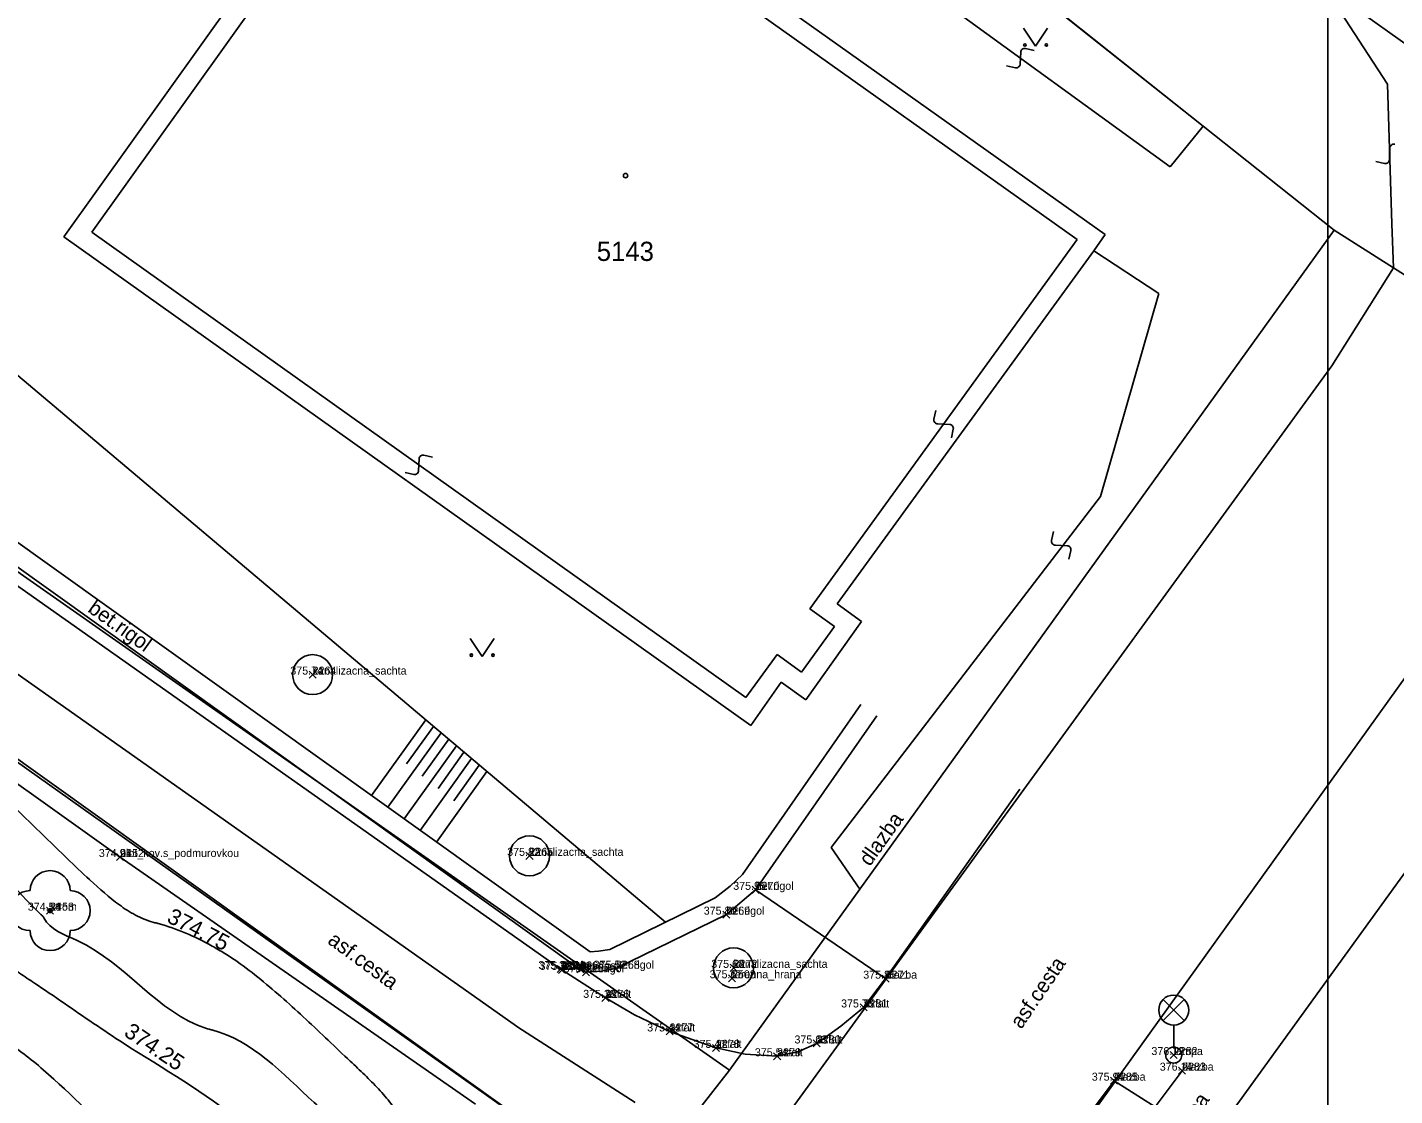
# Model space of a CAD drawing. Extents: x -400488 to -400124, y -1251493 to -1251223.
# Drawn here: x -400282.93 to -400248.76, y -1251353.83 to -1251327.13 of the extents above; entities that cross this region are included whole.
import ezdxf

# ---------------------------------------------------------------- set-up
doc = ezdxf.new("R2010")
doc.units = 0
for name, color, linetype in [('Level 20', 7, 'Continuous'), ('Level 21', 7, 'Continuous'), ('Level 22', 7, 'Continuous'), ('Level 23', 7, 'Continuous'), ('Level 3', 7, 'Continuous'), ('Level 31', 7, 'Continuous'), ('Level 32', 7, 'Continuous'), ('Level 35', 7, 'Continuous'), ('Level 36', 7, 'Continuous'), ('Level 49', 7, 'Continuous'), ('Level 52', 7, 'Continuous'), ('Level 53', 7, 'Continuous'), ('Level 63', 7, 'Continuous')]:
    doc.layers.add(name, color=color, linetype=linetype)

msp = doc.modelspace()

# ---------------------------------------------------------------- linework, layer by layer
at = {"layer": 'Level 20'}
for p, q in [((-400275.888, -1251343.398), (-400275.712, -1251343.222)), ((-400275.712, -1251343.398), (-400275.888, -1251343.222)), ((-400280.698, -1251347.958), (-400280.522, -1251347.782)), ((-400280.522, -1251347.958), (-400280.698, -1251347.782)), ((-400270.468, -1251347.928), (-400270.292, -1251347.752)), ((-400270.292, -1251347.928), (-400270.468, -1251347.752)), ((-400264.818, -1251348.778), (-400264.642, -1251348.602)), ((-400264.642, -1251348.778), (-400264.818, -1251348.602)), ((-400282.448, -1251349.298), (-400282.272, -1251349.122)), ((-400282.272, -1251349.298), (-400282.448, -1251349.122)), ((-400265.548, -1251349.398), (-400265.372, -1251349.222)), ((-400265.372, -1251349.398), (-400265.548, -1251349.222)), ((-400269.688, -1251350.758), (-400269.512, -1251350.582)), ((-400269.512, -1251350.758), (-400269.688, -1251350.582)), ((-400269.658, -1251350.778), (-400269.482, -1251350.602)), ((-400269.482, -1251350.778), (-400269.658, -1251350.602)), ((-400269.198, -1251350.768), (-400269.022, -1251350.592)), ((-400269.022, -1251350.768), (-400269.198, -1251350.592)), ((-400269.058, -1251350.838), (-400268.882, -1251350.662)), ((-400268.882, -1251350.838), (-400269.058, -1251350.662)), ((-400268.308, -1251350.748), (-400268.132, -1251350.572)), ((-400268.132, -1251350.748), (-400268.308, -1251350.572)), ((-400265.368, -1251350.728), (-400265.192, -1251350.552)), ((-400265.192, -1251350.728), (-400265.368, -1251350.552)), ((-400265.408, -1251350.988), (-400265.232, -1251350.812)), ((-400265.232, -1251350.988), (-400265.408, -1251350.812)), ((-400261.568, -1251350.998), (-400261.392, -1251350.822)), ((-400261.392, -1251350.998), (-400261.568, -1251350.822)), ((-400268.568, -1251351.478), (-400268.392, -1251351.302)), ((-400268.392, -1251351.478), (-400268.568, -1251351.302)), ((-400262.118, -1251351.718), (-400261.942, -1251351.542)), ((-400261.942, -1251351.718), (-400262.118, -1251351.542)), ((-400266.968, -1251352.318), (-400266.792, -1251352.142)), ((-400266.792, -1251352.318), (-400266.968, -1251352.142)), ((-400265.808, -1251352.728), (-400265.632, -1251352.552)), ((-400265.632, -1251352.728), (-400265.808, -1251352.552)), ((-400263.288, -1251352.618), (-400263.112, -1251352.442)), ((-400263.112, -1251352.618), (-400263.288, -1251352.442)), ((-400254.368, -1251352.908), (-400254.192, -1251352.732)), ((-400254.192, -1251352.908), (-400254.368, -1251352.732)), ((-400264.278, -1251352.938), (-400264.102, -1251352.762)), ((-400264.102, -1251352.938), (-400264.278, -1251352.762)), ((-400255.858, -1251353.548), (-400255.682, -1251353.372)), ((-400255.682, -1251353.548), (-400255.858, -1251353.372)), ((-400254.158, -1251353.298), (-400253.982, -1251353.122)), ((-400253.982, -1251353.298), (-400254.158, -1251353.122))]:
    msp.add_line(p, q, dxfattribs=at)
at = {"layer": 'Level 3'}
msp.add_lwpolyline([(-400397.431, -1251233.087), (-400250.431, -1251233.087), (-400250.431, -1251440.987), (-400397.431, -1251440.987)], close=True, dxfattribs=at)
at = {"layer": 'Level 31'}
for p, q in [((-400272.972, -1251344.443), (-400274.326, -1251346.336)), ((-400272.59, -1251344.766), (-400273.92, -1251346.625)), ((-400272.781, -1251344.605), (-400273.452, -1251345.543)), ((-400272.208, -1251345.088), (-400273.515, -1251346.915)), ((-400272.399, -1251344.927), (-400273.058, -1251345.849)), ((-400271.826, -1251345.411), (-400273.109, -1251347.205)), ((-400272.017, -1251345.249), (-400272.665, -1251346.155)), ((-400271.444, -1251345.733), (-400272.704, -1251347.495)), ((-400271.635, -1251345.572), (-400272.271, -1251346.461))]:
    msp.add_line(p, q, dxfattribs=at)
for points in [[(-400318.26, -1251315.35), (-400312.96, -1251313.03), (-400288.36, -1251331.46), (-400266.982, -1251349.498)], [(-400316.14, -1251315.89), (-400316.44, -1251316.29), (-400297.85, -1251330.26), (-400287.82, -1251337.3), (-400269.11, -1251350.68), (-400268.97, -1251350.75), (-400268.595, -1251350.721), (-400268.22, -1251350.66), (-400265.46, -1251349.31), (-400264.73, -1251348.69)], [(-400316.14, -1251315.89), (-400297.556, -1251329.855), (-400287.531, -1251336.892), (-400268.865, -1251350.24), (-400268.655, -1251350.224), (-400268.373, -1251350.178), (-400265.736, -1251348.888), (-400265.364, -1251348.599), (-400265.054, -1251348.309), (-400262.095, -1251344.059)], [(-400261.696, -1251344.337), (-400264.73, -1251348.69), (-400261.48, -1251350.91)], [(-400254.07, -1251353.21), (-400254.74, -1251354.11), (-400255.77, -1251353.46)]]:
    msp.add_lwpolyline(points, dxfattribs=at)
at = {"layer": 'Level 32'}
for points in [[(-400312.5, -1251319.48), (-400297.6, -1251330.92), (-400269.6, -1251350.67), (-400269.57, -1251350.69), (-400268.48, -1251351.39), (-400267.759, -1251351.812), (-400266.88, -1251352.23), (-400265.72, -1251352.64), (-400264.993, -1251352.795), (-400264.19, -1251352.85), (-400263.653, -1251352.732), (-400263.2, -1251352.53), (-400262.601, -1251352.1), (-400262.03, -1251351.63), (-400261.48, -1251350.91)], [(-400313.317, -1251321.122), (-400298.667, -1251332.37), (-400270.618, -1251352.155), (-400270.556, -1251352.196), (-400267.742, -1251354.003)], [(-400261.48, -1251350.91), (-400258.127, -1251346.175)], [(-400255.77, -1251353.46), (-400257.84, -1251356.24)]]:
    msp.add_lwpolyline(points, dxfattribs=at)
at = {"layer": 'Level 35'}
for points in [[(-400271.73, -1251354.05), (-400280.61, -1251347.87), (-400289.94, -1251341.22), (-400298.73, -1251334.93), (-400304.55, -1251330.65), (-400304.36, -1251330.4)], [(-400304.36, -1251330.4), (-400289.76, -1251340.83), (-400270.68, -1251354.37)]]:
    msp.add_lwpolyline(points, dxfattribs=at)
at = {"layer": 'Level 36'}
for q in [(-400271.863, -1251342.404), (-400271.263, -1251342.404)]:
    msp.add_line((-400271.563, -1251342.854), q, dxfattribs=at)
for centre, radius in [((-400271.833, -1251342.824), 0.03), ((-400271.293, -1251342.824), 0.03), ((-400282.36, -1251349.21), 0.05)]:
    msp.add_circle(centre, radius, dxfattribs=at)
for centre, start, end in [((-400282.36, -1251348.71), 0, 180), ((-400282.86, -1251349.21), 90, 270), ((-400281.86, -1251349.21), 270, 90), ((-400282.36, -1251349.71), 180, 0)]:
    msp.add_arc(centre, 0.5, start, end, dxfattribs=at)
at = {"layer": 'Level 49'}
for points in [[(-400278.631, -1251370.004), (-400278.118, -1251366.954), (-400277.412, -1251363.928), (-400277.404, -1251363.9), (-400277.243, -1251363.447), (-400277.063, -1251363.002), (-400276.883, -1251362.554), (-400276.725, -1251362.096), (-400276.548, -1251361.022), (-400276.561, -1251359.49), (-400276.508, -1251355.66), (-400276.495, -1251355.542), (-400276.499, -1251355.304), (-400276.5, -1251355.302), (-400276.561, -1251355.147), (-400276.562, -1251355.145), (-400276.659, -1251355.037), (-400276.991, -1251354.829), (-400277.106, -1251354.817), (-400277.114, -1251354.814), (-400277.554, -1251354.518), (-400280.527, -1251352.524), (-400282.011, -1251351.524), (-400282.752, -1251351.021), (-400283.123, -1251350.771), (-400283.308, -1251350.645), (-400283.491, -1251350.515), (-400283.5, -1251350.503), (-400283.513, -1251350.487), (-400283.613, -1251350.393), (-400283.723, -1251350.31), (-400283.834, -1251350.228), (-400283.937, -1251350.138), (-400285.14, -1251348.868), (-400286.294, -1251347.546), (-400287.449, -1251346.222), (-400288.656, -1251344.945), (-400289.834, -1251343.824), (-400290.459, -1251343.304), (-400291.116, -1251342.818), (-400291.123, -1251342.814), (-400295.387, -1251340.816), (-400295.481, -1251340.776), (-400295.888, -1251340.55), (-400296.417, -1251340.117), (-400298.55, -1251337.977), (-400299.765, -1251336.773), (-400300.345, -1251336.13), (-400300.624, -1251335.775), (-400300.759, -1251335.587), (-400300.892, -1251335.391), (-400300.889, -1251335.373), (-400300.892, -1251335.36), (-400300.967, -1251335.291), (-400301.043, -1251335.241), (-400301.201, -1251335.182), (-400301.531, -1251335.135), (-400302.215, -1251335.034), (-400302.251, -1251335.031), (-400302.332, -1251334.999), (-400303.687, -1251334.283), (-400305.005, -1251333.533), (-400306.96, -1251332.166)], [(-400282.087, -1251375.169), (-400281.69, -1251370.822), (-400281.381, -1251368.586), (-400280.551, -1251363.9), (-400280.546, -1251363.886), (-400280.15, -1251362.887), (-400279.737, -1251361.896), (-400279.326, -1251360.9), (-400278.941, -1251359.886), (-400278.883, -1251359.562), (-400278.885, -1251359.094), (-400279.241, -1251356.971), (-400279.631, -1251356.354), (-400280.512, -1251355.223), (-400282.534, -1251353.186), (-400283.018, -1251352.792), (-400283.53, -1251352.437), (-400284.027, -1251352.07), (-400284.466, -1251351.641), (-400284.483, -1251351.618), (-400284.488, -1251351.612), (-400285.314, -1251350.99), (-400287.151, -1251349.31), (-400292.845, -1251345.168), (-400292.862, -1251345.159), (-400295.431, -1251343.95), (-400295.488, -1251343.921), (-400297.591, -1251342.594), (-400300.391, -1251340.357), (-400303.398, -1251337.509), (-400303.407, -1251337.499), (-400305.011, -1251335.906), (-400306.002, -1251335.061), (-400307.028, -1251334.259), (-400308.006, -1251333.512)], [(-400274.109, -1251364.042), (-400274.008, -1251363.383), (-400273.954, -1251363.053), (-400273.943, -1251362.724), (-400273.958, -1251362.626), (-400273.997, -1251362.507), (-400274.011, -1251362.47), (-400274.012, -1251362.468), (-400274.162, -1251361.825), (-400274.25, -1251361.177), (-400274.313, -1251359.872), (-400274.338, -1251357.988), (-400274.341, -1251357.92), (-400274.598, -1251355.942), (-400274.603, -1251355.924), (-400275.052, -1251354.804), (-400275.058, -1251354.792), (-400275.759, -1251354.005), (-400278.319, -1251352.191), (-400278.397, -1251352.171), (-400278.453, -1251352.154), (-400281.685, -1251349.955), (-400282.516, -1251349.39), (-400282.517, -1251349.388), (-400282.537, -1251349.359), (-400282.59, -1251349.305), (-400284.983, -1251346.43), (-400288.552, -1251342.393)], [(-400271.965, -1251360.814), (-400272.009, -1251360.689), (-400272.186, -1251360.237), (-400272.197, -1251360.198), (-400272.225, -1251359.97), (-400272.697, -1251356.579), (-400272.706, -1251356.547), (-400273.542, -1251354.461), (-400273.554, -1251354.438), (-400273.691, -1251354.234), (-400273.837, -1251354.037), (-400274.155, -1251353.667), (-400274.498, -1251353.316), (-400274.859, -1251352.974), (-400275.963, -1251351.93), (-400277.098, -1251350.932), (-400277.684, -1251350.485), (-400277.992, -1251350.283), (-400278.313, -1251350.095), (-400278.97, -1251349.772), (-400279.657, -1251349.533), (-400279.687, -1251349.525), (-400279.791, -1251349.497), (-400280.227, -1251349.321), (-400280.628, -1251349.067), (-400281.363, -1251348.446), (-400281.375, -1251348.435), (-400282.483, -1251347.375), (-400283.583, -1251346.308), (-400284.682, -1251345.24), (-400284.836, -1251345.091)]]:
    msp.add_spline(points, degree=3, dxfattribs=at)
at = {"layer": 'Level 52'}
for centre in [(-400275.8, -1251343.31), (-400270.38, -1251347.84), (-400265.28, -1251350.64)]:
    msp.add_circle(centre, 0.5, dxfattribs=at)
at = {"layer": 'Level 53'}
for p, q in [((-400254.545, -1251351.96), (-400254.015, -1251351.43)), ((-400254.015, -1251351.43), (-400254.545, -1251351.96)), ((-400254.015, -1251351.96), (-400254.545, -1251351.43)), ((-400254.28, -1251352.07), (-400254.28, -1251352.62))]:
    msp.add_line(p, q, dxfattribs=at)
for centre, radius in [((-400254.28, -1251351.695), 0.375), ((-400254.28, -1251352.82), 0.2)]:
    msp.add_circle(centre, radius, dxfattribs=at)
at = {"layer": 'Level 63'}
for p, q in [((-400255.99, -1251332.31), (-400273.23, -1251320.07)), ((-400273.23, -1251320.07), (-400255.99, -1251332.31)), ((-400273.11, -1251320.77), (-400256.69, -1251332.43)), ((-400273.87, -1251320.97), (-400282.02, -1251332.37)), ((-400282.02, -1251332.37), (-400273.87, -1251320.97)), ((-400281.32, -1251332.25), (-400273.46, -1251321.26)), ((-400260.82, -1251323.81), (-400253.54, -1251329.6)), ((-400253.54, -1251329.6), (-400260.82, -1251323.81)), ((-400254.37, -1251330.62), (-400261.85, -1251325.18)), ((-400248.94, -1251328.55), (-400250.54, -1251326.08)), ((-400237.21, -1251335.61), (-400250.54, -1251326.08)), ((-400258.03, -1251327.15), (-400257.73, -1251327.6)), ((-400257.73, -1251327.6), (-400257.43, -1251327.15)), ((-400308.16, -1251327.55), (-400270.88, -1251354.21)), ((-400270.88, -1251354.21), (-400308.16, -1251327.55)), ((-400258.116, -1251328.047), (-400258.104, -1251327.753)), ((-400257.983, -1251327.659), (-400257.765, -1251327.707)), ((-400258.455, -1251328.093), (-400258.237, -1251328.141)), ((-400248.83, -1251332.04), (-400248.94, -1251328.55)), ((-400253.54, -1251329.6), (-400254.37, -1251330.62)), ((-400253.54, -1251329.6), (-400250.27, -1251332.2)), ((-400250.27, -1251332.2), (-400253.54, -1251329.6)), ((-400248.891, -1251330.442), (-400248.879, -1251330.148)), ((-400249.23, -1251330.488), (-400249.012, -1251330.536)), ((-400265.38, -1251353.2), (-400297.73, -1251330.54)), ((-400297.73, -1251330.54), (-400265.38, -1251353.2)), ((-400262.12, -1251348.67), (-400250.27, -1251332.2)), ((-400250.27, -1251332.2), (-400262.12, -1251348.67)), ((-400250.27, -1251332.2), (-400248.79, -1251333.14)), ((-400248.79, -1251333.14), (-400250.27, -1251332.2)), ((-400248.79, -1251333.14), (-400248.83, -1251332.04)), ((-400282.02, -1251332.37), (-400264.85, -1251344.58)), ((-400264.85, -1251344.58), (-400282.02, -1251332.37)), ((-400264.97, -1251343.88), (-400281.32, -1251332.25)), ((-400256.69, -1251332.43), (-400263.37, -1251341.67)), ((-400256.28, -1251332.72), (-400255.99, -1251332.31)), ((-400255.99, -1251332.31), (-400256.28, -1251332.72)), ((-400262.69, -1251341.54), (-400256.28, -1251332.72)), ((-400256.28, -1251332.72), (-400262.69, -1251341.54)), ((-400256.28, -1251332.72), (-400254.65, -1251333.78)), ((-400248.79, -1251333.14), (-400250.33, -1251335.59)), ((-400248.79, -1251333.14), (-400243.42, -1251336.59)), ((-400243.42, -1251336.59), (-400248.79, -1251333.14)), ((-400254.65, -1251333.78), (-400256.11, -1251338.86)), ((-400250.33, -1251335.59), (-400267.74, -1251359.55)), ((-400260.271, -1251336.923), (-400260.223, -1251336.705)), ((-400259.883, -1251337.056), (-400260.177, -1251337.044)), ((-400259.837, -1251337.395), (-400259.789, -1251337.177)), ((-400273.151, -1251338.212), (-400273.139, -1251337.918)), ((-400273.018, -1251337.824), (-400272.8, -1251337.872)), ((-400244.75, -1251338.16), (-400287.97, -1251398.37)), ((-400273.49, -1251338.258), (-400273.272, -1251338.306)), ((-400256.11, -1251338.86), (-400262.84, -1251347.63)), ((-400257.331, -1251339.955), (-400257.283, -1251339.737)), ((-400253.66, -1251355.39), (-400242.23, -1251339.57)), ((-400242.23, -1251339.57), (-400253.66, -1251355.39)), ((-400256.943, -1251340.087), (-400257.237, -1251340.076)), ((-400256.897, -1251340.426), (-400256.849, -1251340.208)), ((-400263.37, -1251341.67), (-400262.76, -1251342.11)), ((-400262.08, -1251341.98), (-400262.69, -1251341.54)), ((-400262.69, -1251341.54), (-400262.08, -1251341.98)), ((-400262.76, -1251342.11), (-400263.58, -1251343.25)), ((-400263.47, -1251343.94), (-400262.08, -1251341.98)), ((-400262.08, -1251341.98), (-400263.47, -1251343.94)), ((-400264.19, -1251342.81), (-400264.97, -1251343.88)), ((-400263.58, -1251343.25), (-400264.19, -1251342.81)), ((-400264.85, -1251344.58), (-400264.09, -1251343.5)), ((-400264.09, -1251343.5), (-400264.85, -1251344.58)), ((-400264.09, -1251343.5), (-400263.47, -1251343.94)), ((-400263.47, -1251343.94), (-400264.09, -1251343.5)), ((-400262.84, -1251347.63), (-400262.12, -1251348.67)), ((-400265.38, -1251353.2), (-400262.12, -1251348.67)), ((-400262.12, -1251348.67), (-400265.38, -1251353.2)), ((-400270.09, -1251359.2), (-400265.38, -1251353.2)), ((-400265.38, -1251353.2), (-400270.09, -1251359.2))]:
    msp.add_line(p, q, dxfattribs=at)
for centre, radius in [((-400258, -1251327.57), 0.03), ((-400257.46, -1251327.57), 0.03), ((-400267.98, -1251330.836), 0.054)]:
    msp.add_circle(centre, radius, dxfattribs=at)
for centre, start, end in [((-400258.004, -1251327.757), 77.7527, 177.7631), ((-400258.216, -1251328.043), 257.753, 357.7631), ((-400248.779, -1251330.152), 77.7527, 177.7631), ((-400248.991, -1251330.438), 257.753, 357.7631), ((-400260.173, -1251336.944), 167.7527, 267.7631), ((-400259.887, -1251337.156), 347.753, 87.7631), ((-400273.039, -1251337.922), 77.7527, 177.7631), ((-400273.251, -1251338.208), 257.753, 357.7631), ((-400257.233, -1251339.976), 167.7527, 267.7631), ((-400256.947, -1251340.187), 347.753, 87.7631)]:
    msp.add_arc(centre, 0.1, start, end, dxfattribs=at)

# ---------------------------------------------------------------- texts
at = {"layer": 'Level 21'}
for s, p in [('2264', (-400275.8, -1251343.31)), ('2452', (-400280.61, -1251347.87)), ('2265', (-400270.38, -1251347.84)), ('2270', (-400264.73, -1251348.69)), ('2453', (-400282.36, -1251349.21)), ('2269', (-400265.46, -1251349.31)), ('2274', (-400269.6, -1251350.67)), ('2275', (-400269.57, -1251350.69)), ('2266', (-400269.11, -1251350.68)), ('2267', (-400268.97, -1251350.75)), ('2268', (-400268.22, -1251350.66)), ('2272', (-400265.28, -1251350.64)), ('2508', (-400265.32, -1251350.9)), ('2271', (-400261.48, -1251350.91)), ('2276', (-400268.48, -1251351.39)), ('2281', (-400262.03, -1251351.63)), ('2277', (-400266.88, -1251352.23)), ('2280', (-400263.2, -1251352.53)), ('2278', (-400265.72, -1251352.64)), ('2279', (-400264.19, -1251352.85)), ('2282', (-400254.28, -1251352.82)), ('2283', (-400254.07, -1251353.21)), ('2285', (-400255.77, -1251353.46))]:
    msp.add_text(s, height=0.2, dxfattribs=at).set_placement(p)
at = {"layer": 'Level 22'}
for s, p in [('kanalizacna_sachta', (-400275.8, -1251343.31)), ('plot_kov.s_podmurovkou', (-400280.61, -1251347.87)), ('kanalizacna_sachta', (-400270.38, -1251347.84)), ('bet.rigol', (-400264.73, -1251348.69)), ('strom', (-400282.36, -1251349.21)), ('bet.rigol', (-400265.46, -1251349.31)), ('asfalt', (-400269.6, -1251350.67)), ('asfalt', (-400269.57, -1251350.69)), ('bet.rigol', (-400269.11, -1251350.68)), ('bet.rigol', (-400268.97, -1251350.75)), ('bet.rigol', (-400268.22, -1251350.66)), ('terenna_hrana', (-400265.32, -1251350.9)), ('kanalizacna_sachta', (-400265.28, -1251350.64)), ('dlazba', (-400261.48, -1251350.91)), ('asfalt', (-400268.48, -1251351.39)), ('asfalt', (-400262.03, -1251351.63)), ('asfalt', (-400266.88, -1251352.23)), ('asfalt', (-400263.2, -1251352.53)), ('asfalt', (-400265.72, -1251352.64)), ('asfalt', (-400264.19, -1251352.85)), ('lampa', (-400254.28, -1251352.82)), ('dlazba', (-400254.07, -1251353.21)), ('dlazba', (-400255.77, -1251353.46))]:
    msp.add_text(s, height=0.2, dxfattribs=at).set_placement(p)
at = {"layer": 'Level 23'}
for s, p in [('375.74', (-400276.358, -1251343.31)), ('374.91', (-400281.143, -1251347.87)), ('375.82', (-400270.938, -1251347.84)), ('375.95', (-400265.289, -1251348.69)), ('374.54', (-400282.918, -1251349.21)), ('375.80', (-400266.026, -1251349.31)), ('375.38', (-400270.158, -1251350.67)), ('375.38', (-400270.128, -1251350.69)), ('375.41', (-400269.643, -1251350.68)), ('375.43', (-400269.528, -1251350.75)), ('375.52', (-400268.778, -1251350.66)), ('375.68', (-400265.838, -1251350.64)), ('375.67', (-400265.878, -1251350.9)), ('375.85', (-400262.039, -1251350.91)), ('375.38', (-400269.038, -1251351.39)), ('375.76', (-400262.593, -1251351.63)), ('375.44', (-400267.438, -1251352.23)), ('375.63', (-400263.758, -1251352.53)), ('375.47', (-400266.278, -1251352.64)), ('375.54', (-400264.748, -1251352.85)), ('376.12', (-400254.838, -1251352.82)), ('376.14', (-400254.628, -1251353.21)), ('375.94', (-400256.328, -1251353.46))]:
    msp.add_text(s, height=0.2, dxfattribs=at).set_placement(p)
at = {"layer": 'Level 31'}
for s, rotation, p in [('bet.rigol', 324.5461, (-400281.444, -1251341.724)), ('dlazba', 54.566, (-400261.873, -1251348.123)), ('dlazba', 54.566, (-400254.224, -1251355.137))]:
    msp.add_text(s, height=0.375, rotation=rotation, dxfattribs=at).set_placement(p)
at = {"layer": 'Level 32'}
for rotation, p in [(323.6458, (-400275.449, -1251350.011)), (55.8347, (-400258.089, -1251352.189))]:
    msp.add_text('asf.cesta', height=0.375, rotation=rotation, dxfattribs=at).set_placement(p)
at = {"layer": 'Level 49'}
for s, rotation, p in [('374.75', 332.8408, (-400279.468, -1251349.483)), ('374.25', 326.1008, (-400280.54, -1251352.32))]:
    msp.add_text(s, height=0.4, rotation=rotation, dxfattribs=at).set_placement(p)
at = {"layer": 'Level 63'}
msp.add_text('5143', height=0.48, dxfattribs=at).set_placement((-400268.698, -1251332.97))

doc.saveas('drawing.dxf')
